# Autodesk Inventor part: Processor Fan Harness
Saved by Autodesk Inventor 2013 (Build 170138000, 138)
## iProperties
GlobalPropertyList: <PropertyList/>
Key:2|1|1|0|4|0|0|0|18|0|0|0|Level:1: <CableProperty entityType="Connector" version="1.0"><ID editable="" value=""/><UserDefined><Property name="14121" value="0.125 in" unitCategory="14110" original
Key:2|1|1|0|12|0|0|0|2|0|0|0|140|0|0|0|1|0|0|0|Level:2: <CableProperty entityType="Connector" version="1.0"><ID editable="" value=""/><UserDefined/><Name editable="True" value=""/><Refdes editable="True" value="Proce
Created: 2007-02
Part Number: Processor Fan Harness
Document SubType Name: Modeling
Designer: floress
Density: 1 g/cm^3
Material: Allgemein
Author: floress
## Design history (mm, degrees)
workpoint "Work Point1"
workpoint "Work Point2"
sketch "Wire1"
workpoint "Work Point3"
workpoint "Work Point4"
sketch "Wire2"
workpoint "Work Point5"
workpoint "Work Point6"
sketch "Segment1"
workpoint "Work Point7"
workpoint "Work Point8"
workpoint "Work Point9"
workpoint "Work Point10"
workpoint "Work Point11"
workpoint "Work Point12"
workpoint "Work Point13"
workpoint "Work Point14"
workpoint "Work Point15"
workpoint "Work Point16"
workpoint "Work Point17"
workpoint "Work Point18"
workpoint "Work Point19"
workpoint "Work Point20"
workpoint "Work Point21"
workpoint "Work Point22"
workpoint "Work Point23"
workpoint "Work Point24"
workpoint "Work Point25"
workplane "Work Plane2"
sketch "Sketch2"
  geometry: C1 r 0.762 at (0, 0); 1 further point
  constraints: 1 centre point
feature "SweepSrf1" sketch "Sketch2" dims "d0" = 0
workpoint "Work Point26"
workpoint "Work Point27"
workplane "Work Plane3"
sketch "Sketch3"
  geometry: C1 r 0.381 at (0, 0); 1 further point
  constraints: 1 centre point
feature "SweepSrf2" sketch "Sketch3" dims "d1" = 0
workplane "Work Plane4"
sketch "Sketch4"
  geometry: C1 r 0.381 at (0, 0); 1 further point
  constraints: 1 centre point
feature "SweepSrf3" sketch "Sketch4" dims "d2" = 0
workplane "Work Plane5"
sketch "Sketch5"
  geometry: C1 r 0.381 at (0, 0); 1 further point
  constraints: 1 centre point
feature "SweepSrf4" sketch "Sketch5" dims "d3" = 0
workplane "Work Plane6"
sketch "Sketch6"
  geometry: C1 r 0.381 at (0, 0); 1 further point
  constraints: 1 centre point
feature "SweepSrf5" sketch "Sketch6" dims "d4" = 0
body "Srf1"
body "Srf2"
body "Srf3"
body "Srf4"
body "Srf5"
